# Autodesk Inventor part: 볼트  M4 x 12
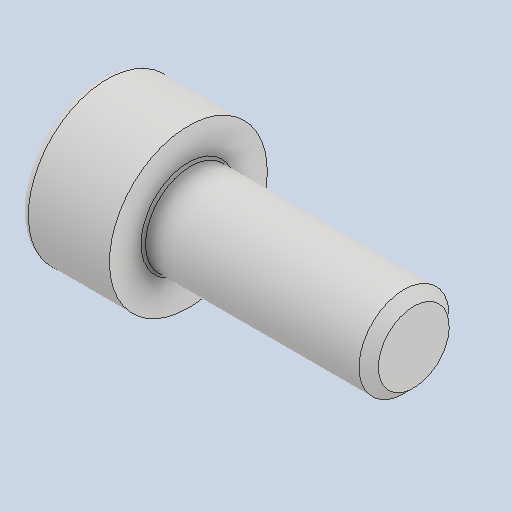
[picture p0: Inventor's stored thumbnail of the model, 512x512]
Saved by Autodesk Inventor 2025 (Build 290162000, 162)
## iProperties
Created: 2024-08
Part Number: 볼트  M4 x 12
Material: 스테인리스강
Description: 6각머리 태핑 나사
Document SubType Name: Modeling
Designer: SAMSUNG
Density: 8.08 g/cm^3
Appearance: 기본값
Author: jhkim
Sending System: Autodesk Inventor 2025
Preprocessor: ST-DEVELOPER v20
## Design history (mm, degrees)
feature "Solid1"
node "솔리드1"
